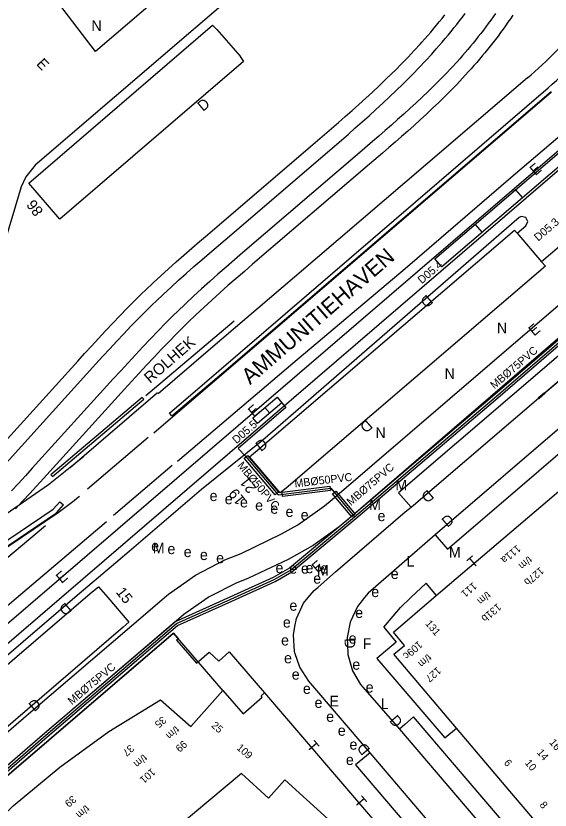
# Model space of a CAD drawing. Extents: x 81617 to 82144, y 454649 to 455150.
# Drawn here: x 81786.6 to 81836.9, y 454780 to 454854.8 of the extents above; entities that cross this region are included whole.
import ezdxf

# ---------------------------------------------------------------- set-up
doc = ezdxf.new("R2010")
doc.units = 0
for name, color, linetype in [('B-WE-OG-TOPOGRAFIE-G', 7, 'Continuous'), ('B-WE-VW-MARKERING-G', 7, 'Continuous'), ('N-OI-KL-VRI_KABEL_DETECTIE-G', 7, 'Continuous'), ('N-OI-KL-VRI_KABELGEUL-G', 7, 'Continuous'), ('N-OI-KL-VRI_LUS_DETECTIE-G', 7, 'Continuous'), ('N-OI-KL-VRI_LUS_DETECTIE-T18', 7, 'Continuous'), ('N-OI-KL-VRI_MANTELBUIS-G', 7, 'Continuous'), ('N-OI-KL-VRI_MANTELBUIS-T18', 7, 'Continuous')]:
    doc.layers.add(name, color=color, linetype=linetype)

msp = doc.modelspace()

# ---------------------------------------------------------------- linework, layer by layer
at = {"layer": 'B-WE-OG-TOPOGRAFIE-G'}
for p, q in [((81805.558, 454853.514), (81807.752, 454850.977)), ((81834.798, 454848.937), (81825.427, 454840.904)), ((81805.738, 454821.365), (81836.744, 454848.02)), ((81805.998, 454821.061), (81837.039, 454847.68)), ((81763.148, 454778.046), (81841.457, 454845.317)), ((81823.838, 454808.513), (81866.813, 454845.385)), ((81764.081, 454776.957), (81842.185, 454844.105)), ((81869.059, 454842.787), (81826.107, 454805.906)), ((81825.427, 454840.904), (81812.88, 454830.176)), ((81833.827, 454834.334), (81836.105, 454831.612)), ((81836.105, 454831.612), (81836.493, 454831.214)), ((81812.88, 454830.176), (81804.962, 454823.429)), ((81804.962, 454823.429), (81800.044, 454819.207)), ((81801.101, 454817.386), (81805.738, 454821.365)), ((81801.338, 454817.106), (81805.998, 454821.061)), ((81801.338, 454817.106), (81801.101, 454817.386)), ((81789.719, 454810.643), (81793.017, 454813.301)), ((81761.696, 454791.345), (81789.719, 454810.643)), ((81804.109, 454810.186), (81797.518, 454804.545)), ((81790.159, 454808.317), (81790.8, 454809.03)), ((81790.8, 454809.03), (81791.135, 454808.729)), ((81765.802, 454791.88), (81790.159, 454808.317)), ((81790.457, 454807.975), (81791.135, 454808.729)), ((81823.302, 454808.086), (81823.838, 454808.513)), ((81766.054, 454791.507), (81790.457, 454807.975)), ((81816.734, 454802.437), (81823.302, 454808.086)), ((81797.518, 454804.545), (81796.054, 454803.292)), ((81796.054, 454803.292), (81792.206, 454800)), ((81823.831, 454800), (81825.273, 454801.371)), ((81826.233, 454800.204), (81825.273, 454801.371)), ((81799.519, 454799.055), (81800.623, 454800)), ((81822.851, 454799.068), (81823.831, 454800)), ((81821.27, 454797.217), (81822.851, 454799.068)), ((81801.036, 454797.199), (81789.381, 454787.24)), ((81821.27, 454797.217), (81822.446, 454795.819)), ((81801.494, 454796.64), (81749.774, 454752.314)), ((81806.144, 454791.235), (81801.488, 454796.641)), ((81822.446, 454795.819), (81820.629, 454794.284)), ((81820.629, 454794.284), (81827.035, 454786.796)), ((81822.76, 454787.622), (81840.998, 454766.241)), ((81827.035, 454786.796), (81828.109, 454787.706)), ((81838.37, 454763.823), (81819.99, 454785.382)), ((81835.644, 454778.819), (81833.126, 454781.789))]:
    msp.add_line(p, q, dxfattribs=at)
for points in [[(81785.704, 454862.502), (81820.842, 454889.264), (81827.718, 454880.146), (81794.137, 454851.447), (81785.704, 454862.502)], [(81830.44, 454877.036), (81829.479, 454875.928), (81828.515, 454875.025), (81818.431, 454866.445), (81788.461, 454840.718), (81787.576, 454839.632), (81787.136, 454838.686)], [(81831.792, 454855.008), (81831.567, 454854.691), (81831.341, 454854.376), (81831.112, 454854.065), (81830.88, 454853.754), (81830.646, 454853.445), (81830.41, 454853.139), (81830.17, 454852.834), (81829.928, 454852.53), (81829.684, 454852.229), (81829.438, 454851.931), (81829.188, 454851.634), (81828.937, 454851.339), (81828.683, 454851.046), (81828.427, 454850.756), (81828.169, 454850.468), (81827.641, 454849.892), (81827.106, 454849.326), (81826.563, 454848.769), (81826.011, 454848.216), (81825.454, 454847.67), (81824.888, 454847.13), (81824.317, 454846.594), (81823.742, 454846.064), (81823.161, 454845.538), (81822.576, 454845.015), (81821.987, 454844.494), (81821.396, 454843.977), (81820.802, 454843.461), (81820.206, 454842.948), (81819.009, 454841.92), (81807.993, 454832.482), (81807.213, 454831.81), (81806.436, 454831.136), (81805.661, 454830.458), (81804.889, 454829.772), (81804.123, 454829.081), (81803.362, 454828.382), (81802.608, 454827.675), (81801.861, 454826.959), (81801.488, 454826.594), (81800.758, 454825.866), (81800.033, 454825.128), (81799.317, 454824.384), (81798.609, 454823.635), (81797.904, 454822.881), (81797.206, 454822.124), (81796.512, 454821.365), (81795.82, 454820.605), (81788.192, 454812.195), (81787.54, 454811.478), (81786.888, 454810.763), (81786.233, 454810.05)], [(81833.419, 454854.84), (81833.194, 454854.51), (81832.966, 454854.183), (81832.735, 454853.857), (81832.502, 454853.533), (81832.266, 454853.211), (81832.027, 454852.891), (81831.786, 454852.573), (81831.542, 454852.257), (81831.295, 454851.943), (81831.046, 454851.631), (81830.795, 454851.321), (81830.541, 454851.013), (81830.284, 454850.707), (81830.025, 454850.403), (81829.763, 454850.101), (81829.499, 454849.802), (81829.232, 454849.504), (81828.691, 454848.914), (81828.142, 454848.333), (81827.585, 454847.761), (81827.021, 454847.196), (81826.451, 454846.638), (81825.875, 454846.088), (81825.295, 454845.543), (81824.71, 454845.004), (81824.121, 454844.471), (81823.529, 454843.942), (81822.935, 454843.417), (81822.339, 454842.895), (81821.741, 454842.376), (81821.142, 454841.86), (81819.943, 454840.831), (81808.928, 454831.394), (81808.152, 454830.725), (81807.379, 454830.054), (81806.61, 454829.381), (81805.846, 454828.703), (81805.089, 454828.02), (81804.338, 454827.33), (81803.595, 454826.634), (81802.86, 454825.929), (81802.497, 454825.573), (81801.776, 454824.855), (81801.062, 454824.128), (81800.355, 454823.393), (81799.654, 454822.652), (81798.956, 454821.905), (81798.263, 454821.153), (81797.572, 454820.398), (81796.882, 454819.64), (81789.254, 454811.23), (81788.601, 454810.512), (81787.946, 454809.794), (81787.287, 454809.077), (81786.625, 454808.363)], [(81799.506, 454827.599), (81799.852, 454827.932), (81800.55, 454828.594), (81801.256, 454829.249), (81801.968, 454829.897), (81802.688, 454830.54), (81803.412, 454831.179), (81804.14, 454831.814), (81804.872, 454832.447), (81806.343, 454833.709), (81815.977, 454841.964), (81816.633, 454842.527), (81817.943, 454843.66), (81818.596, 454844.23), (81819.246, 454844.805), (81819.894, 454845.383), (81820.539, 454845.966), (81821.179, 454846.554), (81821.815, 454847.148), (81822.446, 454847.749), (81823.071, 454848.357), (81823.381, 454848.663), (81823.996, 454849.283), (81824.604, 454849.91), (81825.203, 454850.547), (81825.793, 454851.193), (81825.936, 454851.353), (81826.221, 454851.674), (81826.504, 454851.998), (81826.784, 454852.324), (81827.062, 454852.653), (81827.336, 454852.983), (81827.609, 454853.315), (81827.879, 454853.65), (81828.146, 454853.986), (81828.411, 454854.325), (81828.673, 454854.666), (81828.932, 454855.008)], [(81824.726, 454852.153), (81824.866, 454852.308), (81825.144, 454852.622), (81825.419, 454852.937), (81825.692, 454853.255), (81825.962, 454853.575), (81826.23, 454853.897), (81826.495, 454854.221), (81826.758, 454854.546), (81827.019, 454854.874)], [(81808.083, 454850.503), (81790.784, 454835.636), (81787.871, 454839.036), (81805.141, 454853.917)], [(81805.141, 454853.917), (81805.547, 454853.505), (81805.558, 454853.514)], [(81800.623, 454800), (81801.004, 454800.325), (81803.562, 454802.106), (81806.327, 454803.545), (81807.843, 454804.154), (81811.662, 454806.006), (81813.175, 454806.868), (81815.707, 454808.644), (81816.429, 454809.247), (81868.254, 454853.758)], [(81870.182, 454852.409), (81817.99, 454807.424), (81817.086, 454806.655), (81814.618, 454804.918), (81812.282, 454803.586), (81808.553, 454801.84), (81808.014, 454801.627)], [(81822.972, 454850.287), (81823.566, 454850.901), (81824.151, 454851.523), (81824.726, 454852.152)], [(81807.752, 454850.977), (81807.758, 454850.971), (81808.083, 454850.503)], [(81784.046, 454812.975), (81792.468, 454822.26), (81793.121, 454822.979), (81793.776, 454823.697), (81794.434, 454824.413), (81795.097, 454825.128), (81795.764, 454825.838), (81796.438, 454826.545), (81797.119, 454827.245), (81797.808, 454827.94), (81798.506, 454828.628), (81798.858, 454828.968), (81799.568, 454829.641), (81800.285, 454830.306), (81801.008, 454830.963), (81801.735, 454831.613), (81802.466, 454832.258), (81803.2, 454832.898), (81803.936, 454833.534), (81804.672, 454834.167), (81814.387, 454842.491), (81815.697, 454843.615), (81816.35, 454844.178), (81817.001, 454844.743), (81817.649, 454845.309), (81818.294, 454845.878), (81818.935, 454846.45), (81819.572, 454847.026), (81820.204, 454847.607), (81820.831, 454848.192), (81821.451, 454848.783), (81822.065, 454849.38), (81822.369, 454849.681), (81822.972, 454850.287)], [(81857.884, 454850.147), (81856.226, 454848.756), (81836.105, 454831.612)], [(81866.813, 454845.385), (81865.668, 454846.737), (81822.65, 454809.862), (81823.838, 454808.513)], [(81826.107, 454805.906), (81827.279, 454804.562), (81870.253, 454841.454), (81869.059, 454842.787)], [(81787.136, 454838.686), (81785.453, 454833.006), (81784.632, 454831.127), (81783.463, 454829.444), (81782.809, 454828.741)], [(81833.827, 454834.334), (81834.657, 454835.021), (81834.843, 454835.416), (81834.648, 454835.806), (81834.221, 454835.896), (81834.014, 454835.788), (81809.901, 454814.82), (81804.109, 454810.186)], [(81836.493, 454831.214), (81812.101, 454810.325), (81811.533, 454809.858), (81808.634, 454813.247), (81809.193, 454813.746), (81833.589, 454834.618), (81833.827, 454834.334)], [(81785.108, 454812.01), (81794.182, 454822.013), (81794.835, 454822.728), (81795.489, 454823.44), (81796.146, 454824.149), (81796.807, 454824.852), (81797.472, 454825.55), (81798.143, 454826.241), (81798.821, 454826.924), (81799.506, 454827.598)], [(81807.18, 454826.027), (81798.894, 454819.009)], [(81825.994, 454800), (81848.872, 454819.491), (81848.903, 454819.454)], [(81826.107, 454805.906), (81819.806, 454800.426), (81819.465, 454800)], [(81814.159, 454800), (81814.721, 454800.677), (81815.092, 454800.997), (81816.734, 454802.437)], [(81808.014, 454801.627), (81807.435, 454801.399), (81804.835, 454800.071), (81804.733, 454800)], [(81793.196, 454800), (81793.843, 454800.554), (81794.414, 454801.028), (81795.298, 454800)], [(81792.206, 454800), (81772.929, 454783.504), (81772.8, 454783.04), (81773.052, 454782.628), (81773.524, 454782.531), (81773.713, 454782.605), (81777.521, 454785.862)], [(81777.521, 454785.862), (81777.147, 454786.245), (81793.196, 454800)], [(81795.298, 454800), (81797.285, 454797.69), (81796.739, 454797.205), (81780.048, 454782.872), (81779.695, 454783.314)], [(81804.733, 454800), (81802.441, 454798.4), (81801.036, 454797.199)], [(81812.907, 454797.271), (81813.051, 454798.045), (81813.718, 454799.468), (81814.159, 454800)], [(81819.465, 454800), (81818.79, 454799.155), (81818.113, 454797.675), (81817.828, 454796.24), (81817.881, 454794.727)], [(81833.126, 454781.789), (81822.21, 454794.664), (81823.23, 454795.49), (81822.185, 454796.755), (81825.994, 454800)], [(81724.704, 454738.65), (81731.335, 454743.266), (81747.611, 454754.597), (81760.294, 454765.239), (81787.83, 454789.054), (81799.519, 454799.055)], [(81812.919, 454794.799), (81812.875, 454794.933), (81812.764, 454796.501), (81812.907, 454797.271)], [(81743.995, 454718.166), (81742.77, 454716.807), (81742.397, 454716.287), (81741.864, 454716.67), (81741.739, 454716.768), (81737.992, 454719.956), (81734.516, 454723.438), (81731.335, 454727.19), (81728.469, 454731.189), (81725.937, 454735.407), (81749.774, 454752.314), (81801.494, 454796.64), (81801.921, 454796.142), (81801.754, 454795.999), (81803.633, 454793.814), (81804.829, 454794.852), (81805.754, 454794.029), (81806.738, 454794.89), (81810.035, 454791.045)], [(81819.99, 454785.382), (81814.235, 454792.129), (81813.376, 454793.444), (81812.919, 454794.799)], [(81817.881, 454794.727), (81817.884, 454794.648), (81818.333, 454793.119), (81819.1, 454791.81), (81819.309, 454791.571)], [(81787.201, 454766.106), (81786.818, 454765.785), (81782.717, 454762.276), (81781.508, 454763.7), (81781.148, 454763.366), (81775.464, 454768.491), (81775.701, 454768.759), (81778.464, 454772.224), (81782.289, 454776.45), (81786.401, 454780.398), (81790.78, 454784.047), (81795.403, 454787.381), (81800.249, 454790.382), (81803.118, 454787.854), (81806.132, 454791.265), (81808.027, 454789.057), (81809.844, 454790.62), (81809.721, 454790.765), (81810.035, 454791.045)], [(81819.309, 454791.571), (81822.76, 454787.622)], [(81810.035, 454791.045), (81820.959, 454778.293), (81824.709, 454773.917)], [(81829.229, 454782.739), (81824.078, 454788.772), (81823.257, 454788.056)], [(81823.257, 454788.056), (81822.76, 454787.622)], [(81789.381, 454787.24), (81762.303, 454763.795), (81749.162, 454752.783), (81732.711, 454741.353)], [(81819.99, 454785.382), (81818.61, 454784.24), (81835.737, 454764.161)], [(81801.531, 454763.189), (81816.046, 454779.126), (81811.972, 454782.836), (81810.41, 454781.121), (81807.874, 454783.431), (81790.011, 454768.462)], [(81842.296, 454767.435), (81829.229, 454782.739)]]:
    msp.add_lwpolyline(points, dxfattribs=at)
msp.add_lwpolyline([(81790.082, 454811.4), (81798.676, 454818.679), (81798.533, 454818.848), (81789.939, 454811.569)], close=True, dxfattribs=at)
for centre, radius, start, end in [((81807.049, 454881.413), 42.717, 310.51267, 320.52929), ((81807.67, 454881.636), 44.445, 310.8557, 321.52331)]:
    msp.add_arc(centre, radius, start, end, dxfattribs=at)
at = {"layer": 'B-WE-VW-MARKERING-G'}
for p, q in [((81799.634, 454815.526), (81837.071, 454847.642)), ((81835.851, 454818.772), (81868.247, 454846.483)), ((81836.479, 454819.243), (81836.415, 454819.32)), ((81795.847, 454807.756), (81801.373, 454812.485)), ((81766.082, 454791.465), (81790.622, 454808.026)), ((81770.048, 454790.439), (81789.431, 454806.807))]:
    msp.add_line(p, q, dxfattribs=at)
for points in [[(81801.861, 454812.865), (81812.709, 454822.091), (81823.285, 454831.011), (81833.469, 454839.753), (81842.474, 454847.451), (81852.979, 454856.88)], [(81799.972, 454819.3), (81791.753, 454812.228)], [(81835.819, 454818.81), (81836.414, 454819.32)], [(81835.883, 454818.734), (81836.479, 454819.243)], [(81793.377, 454810.262), (81799.092, 454815.113)], [(81765.349, 454781.943), (81772.75, 454788.148), (81795.193, 454807.165)]]:
    msp.add_lwpolyline(points, dxfattribs=at)
msp.add_arc((81769.517, 454837.768), 36.469, 305.35938, 309.32443, dxfattribs=at)
at = {"layer": 'N-OI-KL-VRI_KABEL_DETECTIE-G'}
msp.add_lwpolyline([(81811.685, 454818.348), (81812.07, 454817.904), (81807.578, 454814.054), (81808.252, 454813.322)], dxfattribs=at)
at = {"layer": 'N-OI-KL-VRI_KABELGEUL-G'}
for points in [[(81733.56, 454760.498), (81731.825, 454758.977), (81732.118, 454758.659), (81742.291, 454747.626), (81742.581, 454747.834), (81749.223, 454752.576), (81762.382, 454763.604), (81782.053, 454780.635), (81789.462, 454787.05), (81795.288, 454792.029), (81801.116, 454797.008), (81801.763, 454797.561), (81806.877, 454799.862), (81810.957, 454801.711), (81812.503, 454802.597), (81818.524, 454807.614), (81831.652, 454818.786), (81838.237, 454824.448)], [(81808.252, 454813.322), (81811.326, 454809.674), (81816.281, 454810.311), (81818.524, 454807.614)]]:
    msp.add_lwpolyline(points, dxfattribs=at)
at = {"layer": 'N-OI-KL-VRI_LUS_DETECTIE-G'}
for p, q in [((81833.684, 454838.397), (81833.432, 454838.181)), ((81833.684, 454838.397), (81834.334, 454837.638)), ((81829.887, 454835.144), (81830.537, 454834.385)), ((81810.087, 454817.912), (81810.087, 454817.912)), ((81810.087, 454817.912), (81810.54, 454817.378))]:
    msp.add_line(p, q, dxfattribs=at)
for points in [[(81826.741, 454831.141), (81826.092, 454831.9), (81841.276, 454844.894), (81841.927, 454844.135)], [(81809.396, 454816.408), (81808.944, 454816.942), (81811.231, 454818.882), (81811.685, 454818.348)]]:
    msp.add_lwpolyline(points, close=True, dxfattribs=at)
at = {"layer": 'N-OI-KL-VRI_MANTELBUIS-G'}
for points in [[(81838.106, 454824.599), (81831.522, 454818.938), (81818.395, 454807.767), (81812.388, 454802.761), (81810.866, 454801.889), (81806.795, 454800.044), (81801.655, 454797.732), (81800.986, 454797.16), (81795.158, 454792.181), (81789.331, 454787.202), (81781.922, 454780.787)], [(81782.184, 454780.484), (81789.592, 454786.898), (81795.418, 454791.877), (81801.246, 454796.856), (81801.871, 454797.391), (81806.96, 454799.679), (81811.048, 454801.532), (81812.618, 454802.432), (81818.653, 454807.461), (81831.782, 454818.634), (81838.367, 454824.296)]]:
    msp.add_lwpolyline(points, dxfattribs=at)
for points in [[(81811.052, 454809.689), (81808.15, 454813.132), (81808.456, 454813.389), (81811.358, 454809.947)], [(81811.698, 454809.924), (81816.196, 454810.502), (81816.247, 454810.105), (81811.749, 454809.527)], [(81818.584, 454807.855), (81818.276, 454807.6), (81816.458, 454809.784), (81816.766, 454810.04)]]:
    msp.add_lwpolyline(points, close=True, dxfattribs=at)

# ---------------------------------------------------------------- texts
at = {"layer": 'B-WE-OG-TOPOGRAFIE-G'}
for s, p in [('N', (81793.757, 454853.369)), ('N', (81831.923, 454824.891)), ('N', (81826.997, 454820.599)), ('N', (81820.496, 454815.024)), ('M', (81822.37, 454810.091)), ('e', (81804.881, 454809.095)), ('e', (81806.31, 454808.796)), ('e', (81807.74, 454808.497)), ('M', (81819.887, 454808.246)), ('e', (81809.17, 454808.198)), ('e', (81810.599, 454807.898)), ('e', (81812.028, 454807.599)), ('e', (81813.458, 454807.3)), ('e', (81820.688, 454807.204)), ('e', (81799.386, 454804.378)), ('M', (81799.528, 454804.174)), ('e', (81800.915, 454804.099)), ('e', (81802.444, 454803.82)), ('M', (81827.407, 454803.779)), ('e', (81803.973, 454803.541)), ('e', (81805.498, 454803.242)), ('L', (81823.429, 454802.923)), ('e', (81811.086, 454802.312)), ('e', (81812.384, 454802.255)), ('e', (81813.478, 454802.257)), ('e', (81813.912, 454802.304)), ('M', (81814.99, 454802.072)), ('e', (81815.298, 454802.265)), ('e', (81821.932, 454801.759)), ('e', (81814.637, 454801.317)), ('e', (81820.1, 454800.052)), ('e', (81812.395, 454798.766)), ('e', (81818.586, 454798.085)), ('e', (81811.78, 454797.184)), ('e', (81817.97, 454795.675)), ('e', (81811.608, 454795.494)), ('F', (81819.29, 454795.176)), ('e', (81811.892, 454793.818)), ('e', (81818.315, 454793.212)), ('e', (81812.612, 454792.277)), ('e', (81819.572, 454791.065)), ('e', (81813.663, 454790.933)), ('e', (81814.759, 454789.619)), ('E', (81816.174, 454789.755)), ('L', (81820.984, 454789.504)), ('e', (81815.855, 454788.306)), ('e', (81816.952, 454786.992)), ('e', (81818.048, 454785.679)), ('e', (81817.71, 454784.238))]:
    msp.add_text(s, height=1, dxfattribs=at).set_placement(p)
for s, height, rotation, p in [('E', 1, 313.13893, (81788.52, 454850.222)), ('D', 1, 40.25715, (81804.265, 454845.736)), ('E', 1, 40.43959, (81835.538, 454839.684)), ('86', 1, 127.33719, (81789.272, 454836.4)), ('AMMUNITIEHAVEN', 1.5, 40.93859, (81808.691, 454820.004)), ('D', 1, 220.89503, (81825.352, 454828.592)), ('E', 1, 40.11439, (81835.42, 454824.574)), ('ROLHEK', 1.05, 40.92747, (81799.278, 454820.121)), ('E', 1, 41.06837, (81809.037, 454816.939)), ('D', 1, 220.82522, (81819.667, 454816.821)), ('D', 1, 38.5926, (81809.711, 454813.703)), ('21', 1, 128.15048, (81809.339, 454810.32)), ('19', 1, 128.15048, (81808.298, 454809.213)), ('D', 1, 220.63643, (81825.439, 454810.223)), ('D', 1, 40.69129, (81827.27, 454806.568)), ('111a', 0.7, 220.42801, (81833.813, 454805.02)), ('T', 1, 40.33818, (81829.658, 454802.722)), ('t/m', 0.7, 220.42801, (81834.879, 454803.958)), ('E', 1, 40.56922, (81815.031, 454802.27)), ('E', 1, 40.07427, (81790.946, 454801.275)), ('127b', 0.7, 220.42801, (81835.991, 454802.934)), ('15', 1, 308.15048, (81796.016, 454800.506)), ('111', 0.7, 220.43092, (81829.675, 454801.494)), ('t/m', 0.7, 220.43092, (81830.98, 454800.635)), ('D', 1, 220.48976, (81791.346, 454799.599)), ('131b', 0.7, 220.43092, (81831.975, 454799.512)), ('131', 0.7, 310.29256, (81825.137, 454797.534)), ('D', 1, 272.02467, (81817.576, 454796.163)), ('109c', 0.7, 221.37923, (81824.539, 454795.973)), ('t/m', 0.7, 221.37923, (81825.407, 454794.739)), ('127', 0.7, 221.37923, (81826.301, 454793.528)), ('D', 1, 40.52516, (81788.389, 454789.197)), ('D', 1, 311.18588, (81821.744, 454788.396)), ('35', 0.7, 221.37507, (81800.428, 454788.873)), ('25', 0.7, 318.60542, (81804.983, 454787.877)), ('t/m', 0.7, 221.37507, (81801.668, 454787.967)), ('T', 1, 310.40944, (81813.968, 454785.987)), ('16', 0.7, 310.29077, (81836.809, 454786.338)), ('37', 0.7, 221.37507, (81797.4, 454786.207)), ('99', 0.7, 221.37507, (81802.387, 454786.601)), ('109', 0.7, 318.60542, (81807.369, 454785.774)), ('D', 1, 130.44965, (81820.051, 454785.703)), ('t/m', 0.7, 221.37507, (81798.639, 454785.299)), ('14', 0.7, 310.29077, (81835.643, 454785.393)), ('6', 0.7, 310.29077, (81832.538, 454784.416)), ('10', 0.7, 310.29077, (81834.511, 454784.409)), ('101', 0.7, 221.37507, (81799.416, 454783.984)), ('T', 1, 310.81502, (81818.439, 454780.764)), ('39', 0.7, 221.37507, (81791.959, 454781.413)), ('8', 0.7, 310.29077, (81835.899, 454780.452)), ('t/m', 0.7, 221.37507, (81793.211, 454780.517))]:
    msp.add_text(s, height=height, rotation=rotation, dxfattribs=at).set_placement(p)
at = {"layer": 'N-OI-KL-VRI_LUS_DETECTIE-T18'}
for s, rotation, p in [('D05.3', 40.59928, (81835.813, 454833.518)), ('D05.4', 40.59928, (81824.852, 454829.503)), ('D05.5', 41.21043, (81807.413, 454814.442))]:
    msp.add_text(s, height=0.75, rotation=rotation, dxfattribs=at).set_placement(p)
at = {"layer": 'N-OI-KL-VRI_MANTELBUIS-T18'}
for s, rotation, p in [('MB%%C75PVC', 40.69, (81831.692, 454819.608)), ('MB%%C50PVC', 310.12, (81807.447, 454812.41)), ('MB%%C75PVC', 40.69, (81818.176, 454808.616)), ('MB%%C50PVC', 6.69242, (81812.916, 454810.378)), ('MB%%C75PVC', 39.96, (81791.918, 454789.856))]:
    msp.add_text(s, height=0.75, rotation=rotation, dxfattribs=at).set_placement(p)

doc.saveas('drawing.dxf')
